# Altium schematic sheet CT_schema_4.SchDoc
size 208 x 169 mm
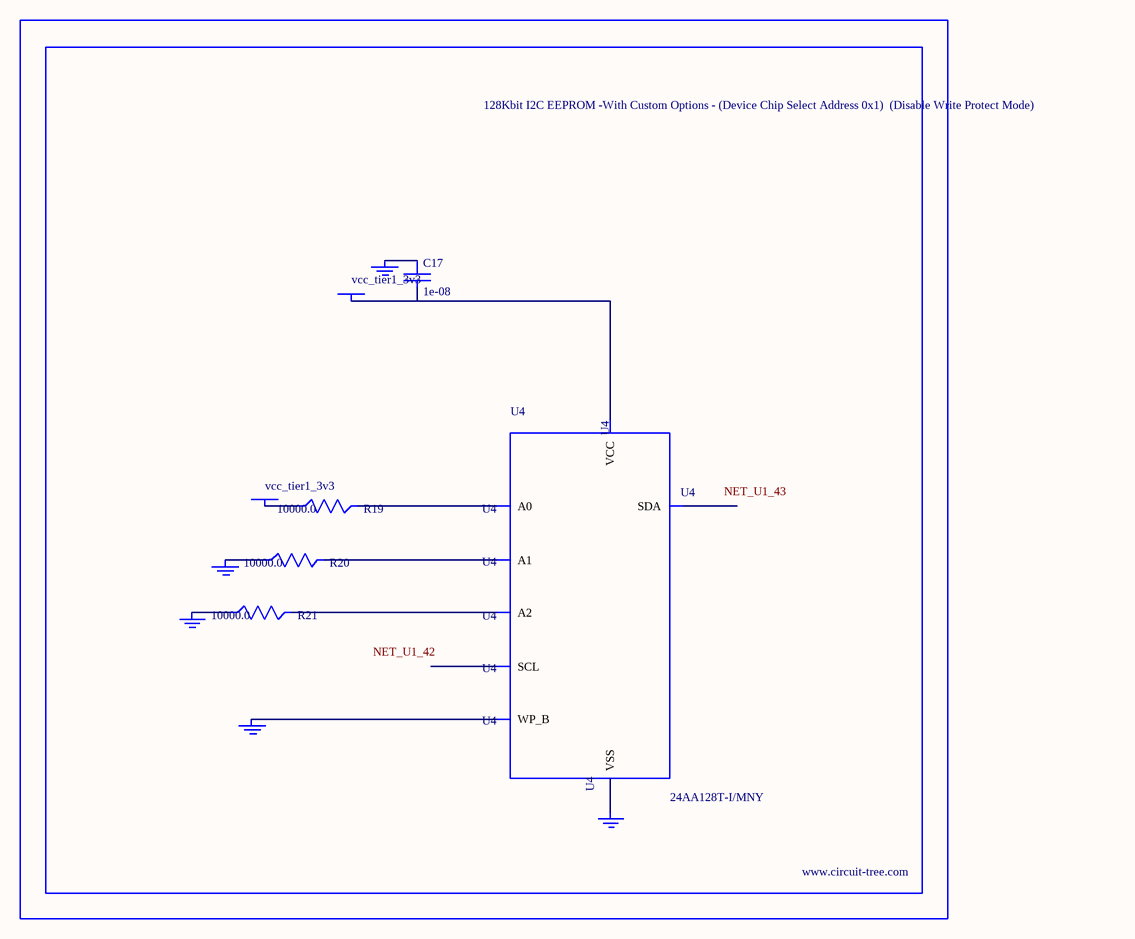
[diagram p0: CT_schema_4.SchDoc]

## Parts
BORDER3  (no value)
C17  1e-08  [C0402]
GND_INSTANCE_3_0  (no value)
GND_INSTANCE_3_1  (no value)
GND_INSTANCE_3_2  (no value)
GND_INSTANCE_3_3  (no value)
GND_INSTANCE_3_4  (no value)
POWER_INSTANCE_3_0  vcc_tier1_3v3
POWER_INSTANCE_3_1  vcc_tier1_3v3
R19  10000.0  [R0603]
R20  10000.0  [R0603]
R21  10000.0  [R0603]
U4  24AA128T-I/MNY  [TDFN-8/6MM]

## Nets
NetC17_1: C17.1 GND_INSTANCE_3_3.0(GND)
NetC17_2: C17.2 POWER_INSTANCE_3_1.0(PWR) U4.8(VCC)
NetGND_INSTANCE_3_0_0: GND_INSTANCE_3_0.0(GND) R20.1
NetGND_INSTANCE_3_1_0: GND_INSTANCE_3_1.0(GND) R21.1
NetGND_INSTANCE_3_2_0: GND_INSTANCE_3_2.0(GND) U4.7(WP_B)
NetGND_INSTANCE_3_4_0: GND_INSTANCE_3_4.0(GND) U4.4(VSS)
NetPOWER_INSTANCE_3_0_0: POWER_INSTANCE_3_0.0(PWR) R19.1
NetR19_2: R19.2 U4.1(A0)
NetR20_2: R20.2 U4.2(A1)
NetR21_2: R21.2 U4.3(A2)

Not connected (* = marked no-connect by the designer): U4 5(SDA) 6(SCL)

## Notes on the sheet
- Labels drawn without touching a wire or pin: NET_U1_42, NET_U1_43

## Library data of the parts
BORDER3 = BORDER_PAGE3
C17 = C0402C103K3RAC
GND_INSTANCE_3_0-GND_INSTANCE_3_4 = GND
POWER_INSTANCE_3_0 POWER_INSTANCE_3_1 = PWR
R19-R21 = RC0603JR-0710KL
